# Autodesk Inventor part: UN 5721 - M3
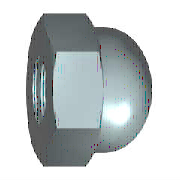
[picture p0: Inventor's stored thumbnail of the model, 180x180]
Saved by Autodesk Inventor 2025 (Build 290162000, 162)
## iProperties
Created: 2024-01
Part Number: UN 5721 - M3
Material: Acciaio, Dolce
Description: Dado esagonale con calotta sferica
Document SubType Name: Modeling
Standard: UN 5721
Designer: R5800u
Standards Organization: UNI
Language: it-IT
Size Designation: M3
Categories: <MemberInstance><Categories><Category DisplayName="Elementi di fissaggio" InternalName="e4da775c-781d-43d5-af7c-5136215cf5a6" Mnemonic="FSTN"><Category DisplayN
Density: 7.85 g/cm^3
Appearance: Semilucidato
IsCustomPart: 0
Author: R5800u
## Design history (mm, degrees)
body "Solid1"
sketch "Schizzo3"
  geometry: L1 (0, -4.446)-(0, 4.446) reference; L2 (-3.85, 0)-(3.85, 0) reference; 1 further point
  constraints: 2 midpoint
hole "Filettatura" sketch "Schizzo3" diameter "d24" = 2.459; stored, may be unused: drill point angle "d13" = 120 deg, countersink angle "d28" = 82 deg; dims "d11" = 4 (= GEL), "d12" = 4.08 (= 1.02 x GEL), "d26" = 4, "d27" = 2
workaxis "Work Axis1"
workplane "Work Plane1"
sketch "Schizzo1"
  geometry: L1 (-1.588, -2.75)-(-3.175, 0); L2 (-3.175, 0)-(-1.588, 2.75); L3 (-1.588, 2.75)-(1.588, 2.75); L4 (1.588, 2.75)-(3.175, 0); L5 (3.175, 0)-(1.588, -2.75); L6 (1.588, -2.75)-(-1.588, -2.75); 2 further points
  constraints: 12 end point, 1 coincident, 1 horizontal, 11 other
  dimensions: "d0" = 6.35085 distance of L4.end L1.end (= 1.1547 x SW)
extrude "Corpo" new body sketch "Schizzo1" distance "d1" = 2.4 (= SIH); taper "d2" = 0 deg
revolve "Smusso1" stored, may be unused: angle "d7" = 90 deg
revolve "Calotta" stored, may be unused: angle "d10" = 180 deg
chamfer "Smusso2" distance "d14" = 0.27063 (= -0.5 x GD1 + 0.5 x NND); stored, may be unused: angle "d15" = 30 deg, second distance "d36" = 0.27063 (= -0.5 x GD1 + 0.5 x NND)
sketch "Schizzo4"
  geometry: L1 (0, 1.588)-(0, 3.175) reference; L2 (0, 3.175)-(2.4, 3.175) reference; L3 (2.4, 1.588)-(2.4, 3.175) reference; L4 (-0.48, 0)-(2.88, 0) reference; L5 (0.246, 3.175)-(0, 2.75); L6 (2.154, 3.175)-(2.4, 2.75)
  constraints: 4 end point, 4 point on line, 1 horizontal alignment
  dimensions: "d3" = 5.5 diameter of L5.end L4 (= SW0); "d4" = 30 deg angle of L5 L1 (= ANG1); "d5" = 5.5 diameter of L6.end L4 (= SW01); "d6" = 30 deg angle of L3 L6 (= ANG2)
sketch "Schizzo2"
  geometry: L1 (2.4, 0)-(6.5, 0); L2 (4, 2.5)-(2.4, 2.5); L3 (2.4, -1.588)-(2.4, 1.588) reference; L4 (2.4, 0)-(2.4, 2.5); L5 (1.476, 0)-(7.941, 0) reference; A1 r 2.5 centre (4, 0) between (6.5, 0) and (4, 2.5)
  constraints: 6 end point, 2 collinear, 2 point on circle, 1 centre point, 1 horizontal, 1 midpoint, 1 point on line, 1 tangent
  dimensions: "d8" = 2.5 radius of A1 (= KR); "d9" = 4.1 distance from line of L1.end L4 (= KOH1 - SIH)
other parameters: "ANG1" = 30 deg [user parameter; used in 1 equation term], "ANG2" = 30 deg [user parameter; used in 1 equation term], "NND" = 3 [user parameter; used in 2 equation terms], "SIH" = 2.4 [user parameter; used in 2 equation terms], "KOH1" = 6.5 [user parameter; used in 1 equation term], "GEL" = 4 [user parameter; used in 2 equation terms], "SW" = 5.5 [user parameter; used in 4 equation terms], "KR" = 2.5 [user parameter; used in 1 equation term], "SW0" = 5.5 (= SW) [user parameter; used in 1 equation term], "SW01" = 5.5 (= SW) [user parameter; used in 1 equation term], "GD1" = 2.45873 (computed from THREADDIA, PTC, TOA) [user parameter; used in 2 equation terms], "d16" = 0, "d35" = 0, "d37" = 0, "GUL" = 0.27063 (= 0.541266 x PTC) [user parameter], "THREADDIA" = 3 [user parameter; used in 1 equation term], "TOA" = 30 deg [user parameter; used in 1 equation term], "PTC" = 0.5 [user parameter; used in 4 equation terms], "E0" = 6.3525 (= 1.155 x SW) [user parameter], "GAL" = 0.27063 (= 0.541266 x PTC) [user parameter]
